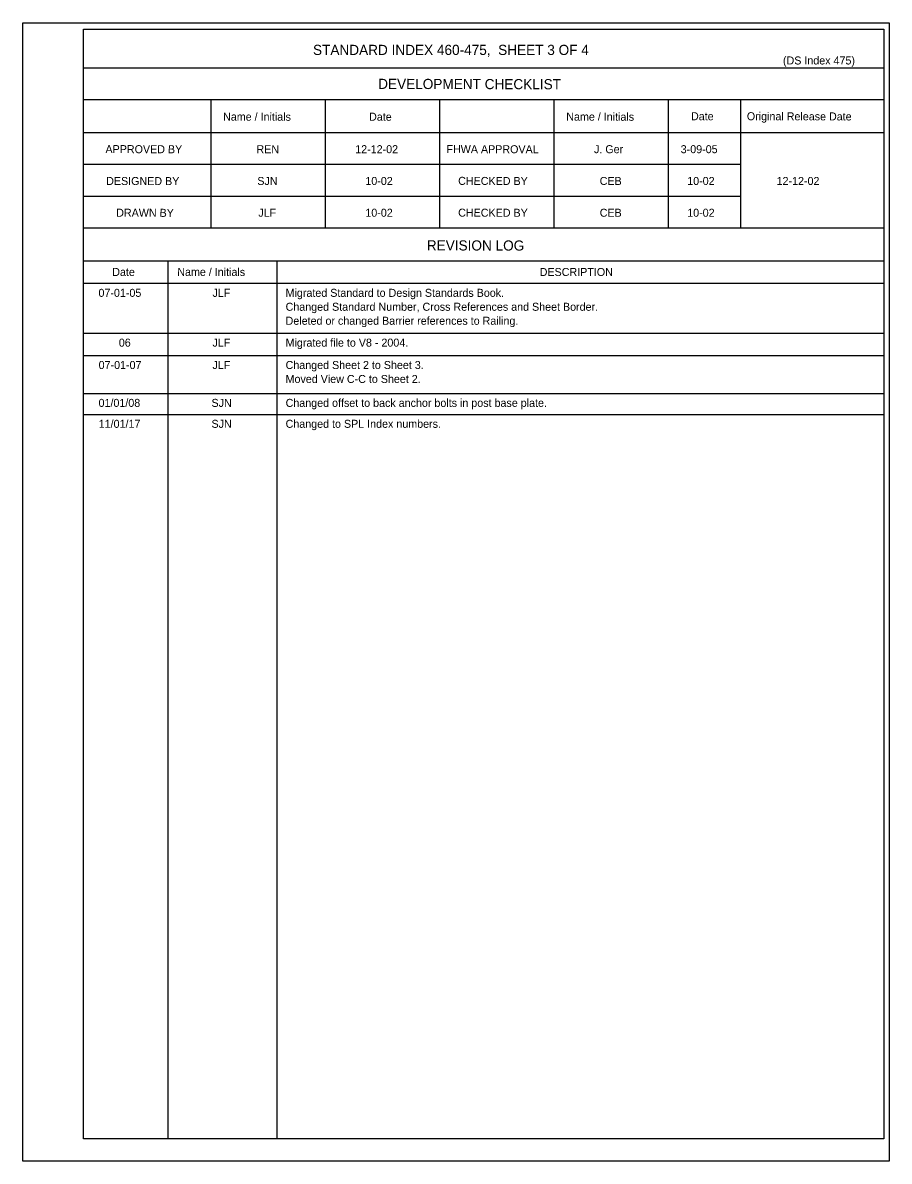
# Model space of a CAD drawing. Extents: x 21526.6 to 21598.7, y 56118.9 to 56155.9.
# Drawn here: x 21576.91 to 21598.72, y 56124.63 to 56153.3 of the extents above; entities that cross this region are included whole.
import ezdxf

# ---------------------------------------------------------------- set-up
doc = ezdxf.new("R2010")
doc.units = 0
doc.layers.add('Border', color=7, linetype='Continuous')
doc.layers.add('PlotBorder_dp', color=7, linetype='Continuous')

msp = doc.modelspace()

# ---------------------------------------------------------------- linework, layer by layer
at = {"layer": 'Border'}
for p, q in [((21598.589, 56152.158), (21578.442, 56152.158)), ((21598.589, 56151.358), (21578.442, 56151.358)), ((21581.642, 56151.358), (21581.642, 56148.13)), ((21584.522, 56151.358), (21584.522, 56148.13)), ((21587.402, 56151.358), (21587.402, 56148.13)), ((21590.282, 56151.358), (21590.282, 56148.13)), ((21593.162, 56151.358), (21593.162, 56148.13)), ((21594.977, 56151.358), (21594.977, 56148.13)), ((21598.589, 56150.53), (21578.442, 56150.53)), ((21594.977, 56149.73), (21578.442, 56149.73)), ((21594.977, 56148.93), (21578.442, 56148.93)), ((21598.589, 56148.13), (21578.442, 56148.13)), ((21598.589, 56147.302), (21578.442, 56147.302)), ((21580.562, 56147.302), (21580.562, 56125.196)), ((21583.304, 56147.302), (21583.304, 56125.196)), ((21598.589, 56146.738), (21578.442, 56146.738))]:
    msp.add_line(p, q, dxfattribs=at)
msp.add_lwpolyline([(21578.442, 56153.138), (21598.589, 56153.138), (21598.589, 56125.196), (21578.442, 56125.196)], close=True, dxfattribs=at)
at = {"layer": 'PlotBorder_dp'}
for p, q in [((21578.442, 56145.484), (21598.589, 56145.484)), ((21578.442, 56144.921), (21598.589, 56144.921)), ((21578.442, 56143.967), (21598.589, 56143.967)), ((21578.442, 56143.44), (21598.589, 56143.44)), ((21576.911, 56124.634), (21576.911, 56124.634))]:
    msp.add_line(p, q, dxfattribs=at)
msp.add_lwpolyline([(21576.911, 56153.301), (21598.725, 56153.301), (21598.725, 56124.634), (21576.911, 56124.634)], close=True, dxfattribs=at)

# ---------------------------------------------------------------- texts
at = {"layer": 'Border'}
for s, height, p in [('STANDARD INDEX 460-475,  SHEET 3 OF 4', 0.256, (21584.218, 56152.49)), ('(DS Index 475)', 0.2016, (21596.049, 56152.251)), ('REN', 0.2016, (21582.794, 56150.017)), ('12-12-02', 0.2016, (21585.281, 56150.017)), ('J. Ger', 0.2016, (21591.292, 56150.017)), ('3-09-05', 0.2016, (21593.475, 56150.017)), ('SJN', 0.2016, (21582.816, 56149.217)), ('10-02', 0.2016, (21585.536, 56149.217)), ('CEB', 0.2016, (21591.436, 56149.217)), ('10-02', 0.2016, (21593.639, 56149.217)), ('12-12-02', 0.2016, (21595.889, 56149.217)), ('JLF', 0.2016, (21582.841, 56148.417)), ('10-02', 0.2016, (21585.536, 56148.417)), ('CEB', 0.2016, (21591.436, 56148.417)), ('10-02', 0.2016, (21593.639, 56148.417)), ('DESCRIPTION', 0.2016, (21589.925, 56146.925)), ('07-01-05', 0.2016, (21578.817, 56146.4)), ('JLF', 0.2016, (21581.688, 56146.4)), ('Migrated Standard to Design Standards Book.', 0.2016, (21583.528, 56146.4)), ('Changed Standard Number, Cross References and Sheet Border.', 0.2016, (21583.528, 56146.049)), ('Deleted or changed Barrier references to Railing.', 0.2016, (21583.528, 56145.697)), ('06', 0.2016, (21579.329, 56145.146)), ('JLF', 0.2016, (21581.688, 56145.146)), ('Migrated file to V8 - 2004.', 0.2016, (21583.528, 56145.146)), ('07-01-07', 0.2016, (21578.821, 56144.583)), ('JLF', 0.2016, (21581.688, 56144.583)), ('Changed Sheet 2 to Sheet 3.', 0.2016, (21583.528, 56144.583)), ('Moved View C-C to Sheet 2.', 0.2016, (21583.528, 56144.231)), ('01/01/08', 0.2016, (21578.819, 56143.629)), ('SJN', 0.2016, (21581.663, 56143.629)), ('Changed offset to back anchor bolts in post base plate.', 0.2016, (21583.528, 56143.629)), ('11/01/17', 0.2016, (21578.823, 56143.102)), ('SJN', 0.2016, (21581.663, 56143.102)), ('Changed to SPL Index numbers.', 0.2016, (21583.528, 56143.102))]:
    msp.add_text(s, height=height, dxfattribs=at).set_placement(p)
for s, height, p in [('DEVELOPMENT CHECKLIST', 0.256, (21585.858, 56151.635)), ('Name / Initials', 0.2016, (21581.954, 56150.837)), ('Date', 0.2016, (21585.629, 56150.835)), ('Name / Initials', 0.2016, (21590.594, 56150.837)), ('Date', 0.2016, (21593.734, 56150.847)), ('Original Release Date', 0.2016, (21595.14, 56150.847)), ('APPROVED BY', 0.2016, (21578.993, 56150.019)), ('FHWA APPROVAL', 0.2016, (21587.577, 56150.019)), ('DESIGNED BY', 0.2016, (21579.01, 56149.217)), ('CHECKED BY', 0.2016, (21587.872, 56149.219)), ('DRAWN BY', 0.2016, (21579.263, 56148.417)), ('CHECKED BY', 0.2016, (21587.872, 56148.419)), ('REVISION LOG', 0.256, (21587.083, 56147.569)), ('Date', 0.2016, (21579.164, 56146.926)), ('Name / Initials', 0.2016, (21580.801, 56146.928))]:
    msp.add_text(s, height=height, rotation=359.8756, dxfattribs=at).set_placement(p)

doc.saveas('drawing.dxf')
